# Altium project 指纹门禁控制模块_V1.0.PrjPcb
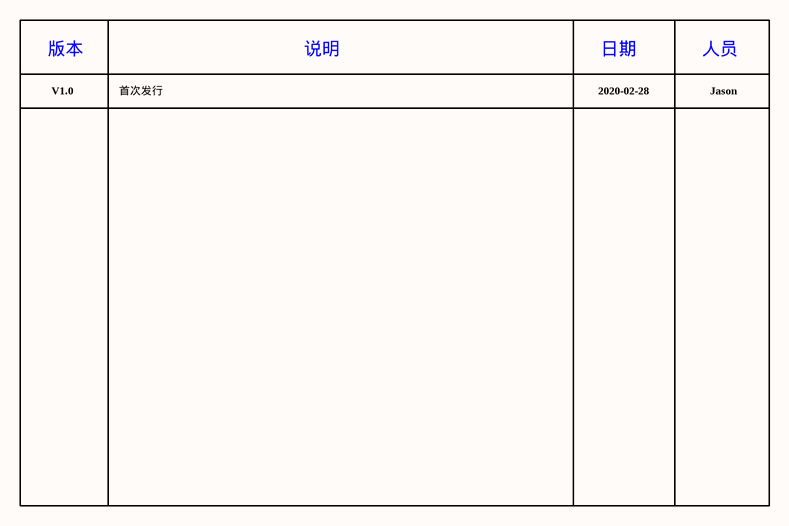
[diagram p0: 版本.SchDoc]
2 sheets, 45 parts. Net scope: global (net labels, ports and power ports of the same name join across sheets).
Board file: 指纹门禁控制模块_V1.0.PcbDoc
Sheets:
  版本.SchDoc
  指纹门禁控制模块_V1.0.SchDoc

## Sheet 版本.SchDoc
size A4

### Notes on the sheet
- 版本
- V1.0
- 首次发行
- 说明
- 2020-02-28
- 日期
- 人员
- Jason

## Sheet 指纹门禁控制模块_V1.0.SchDoc
size A3
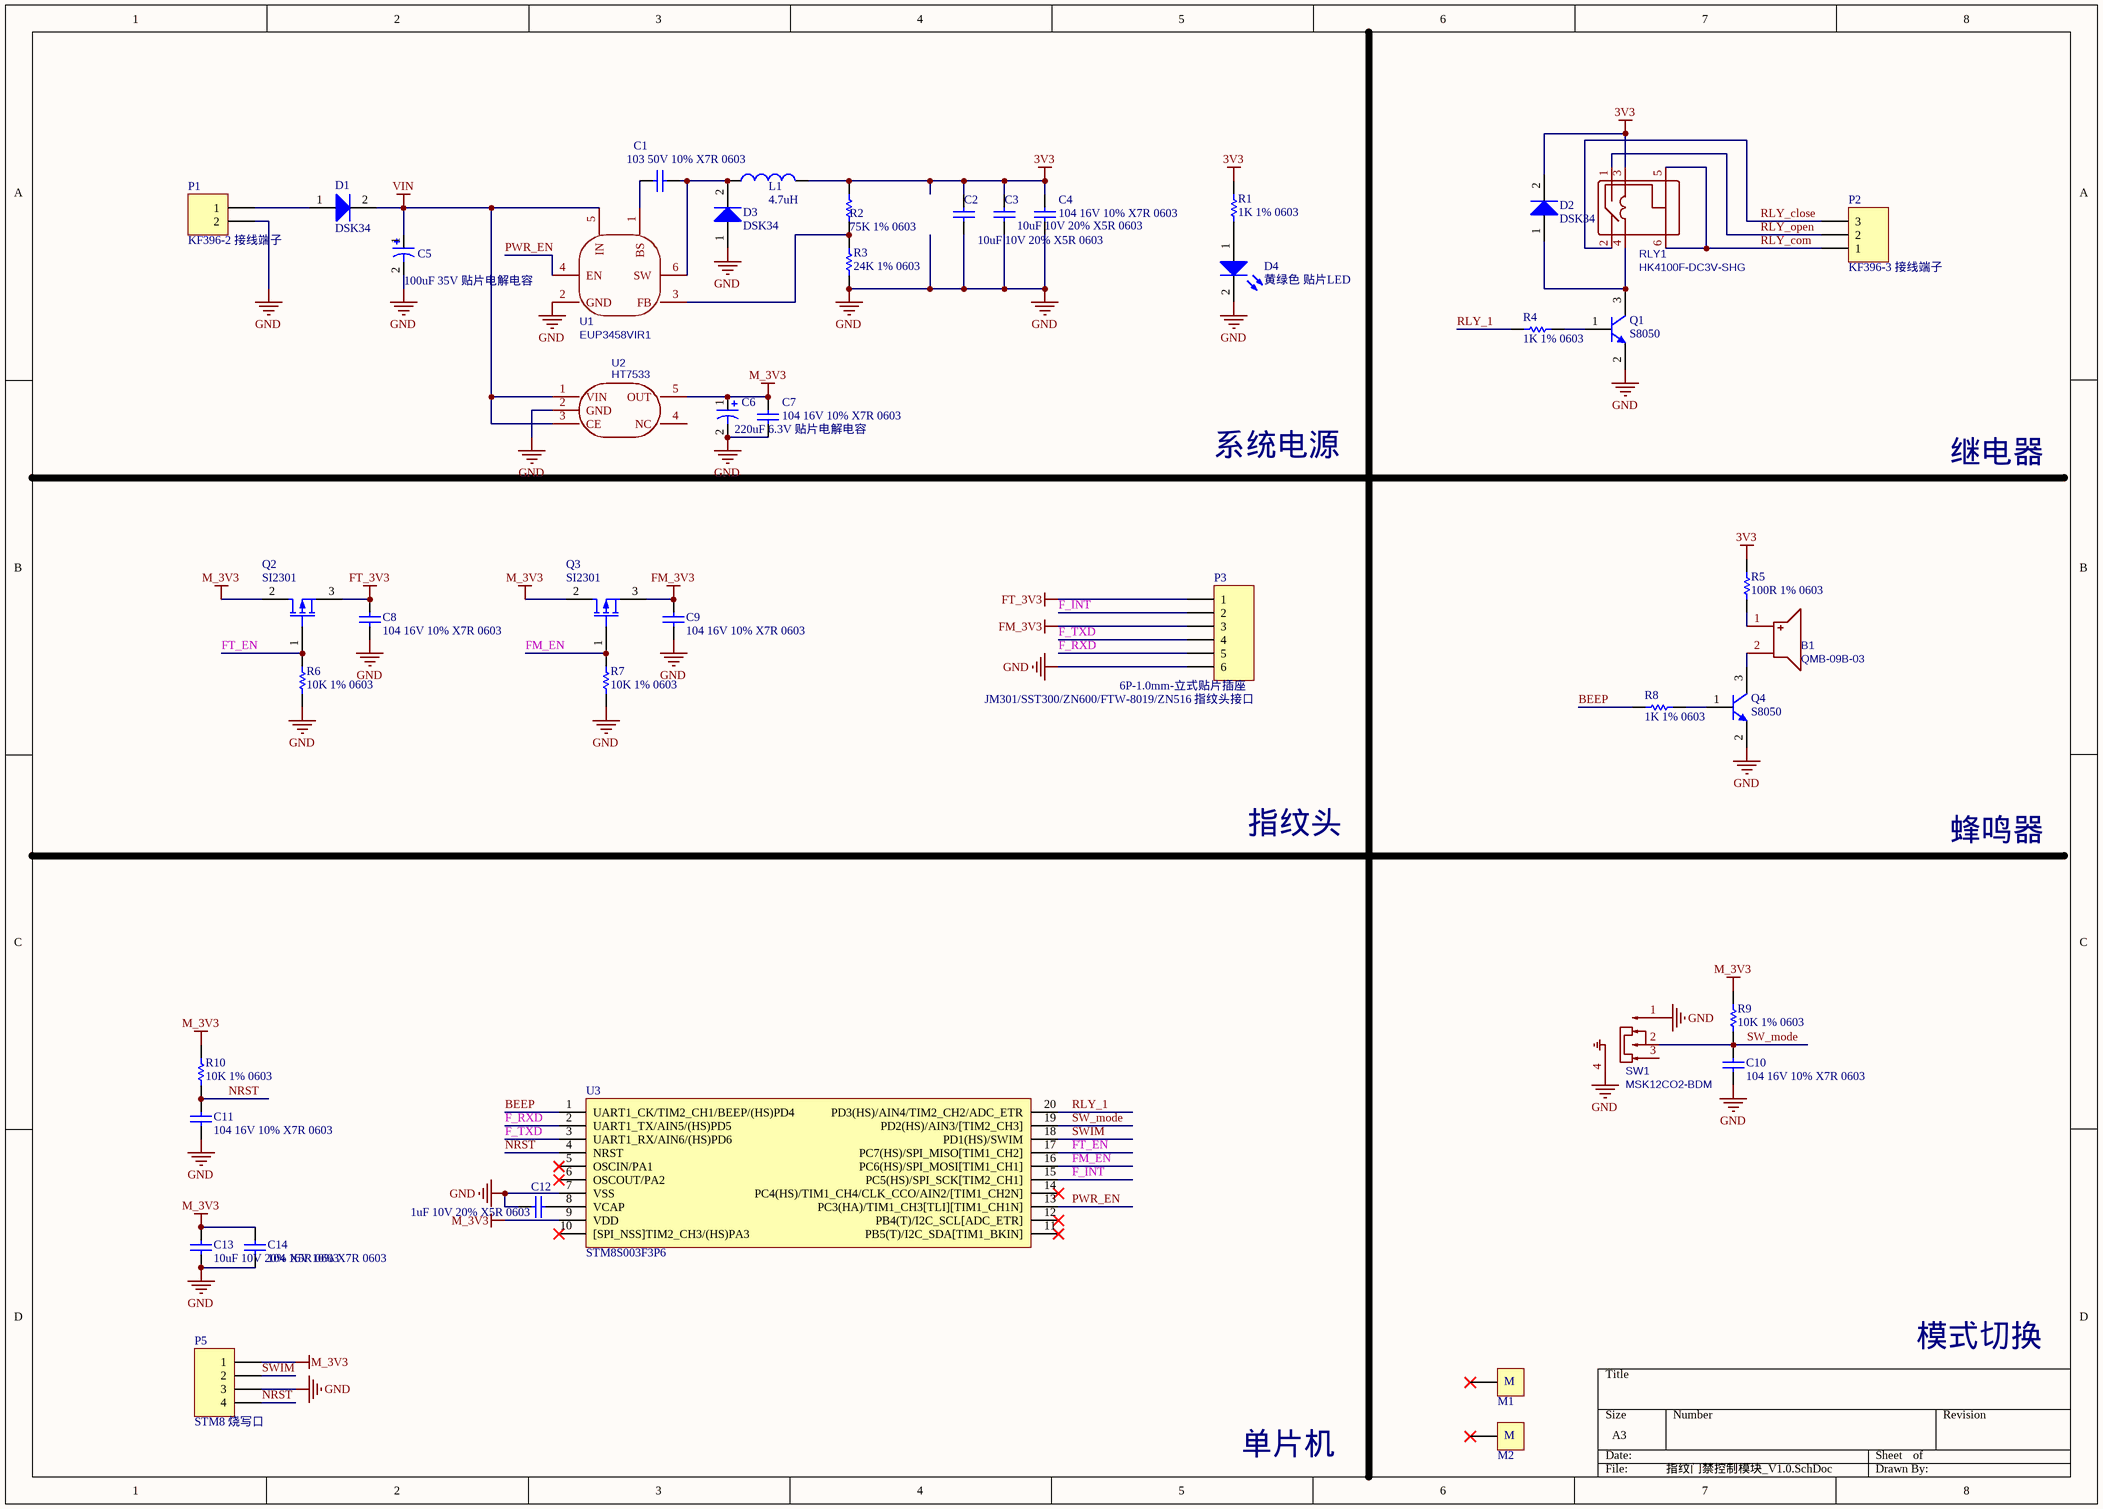
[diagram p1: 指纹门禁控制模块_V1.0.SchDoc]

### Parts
B1  QMB-09B-03  [BUZZER-9MM]
C1  103 50V 10% X7R 0603  [C0603]
C2  10uF 10V 20% X5R 0603  [C0603]
C3  10uF 10V 20% X5R 0603  [C0603]
C4  104 16V 10% X7R 0603  [C0603]
C5  100uF 35V 贴片电解电容  [CAP-D6.3XH7.7]
C6  220uF 6.3V 贴片电解电容  [CAP-D6.3XH7.7]
C7  104 16V 10% X7R 0603  [C0603]
C8  104 16V 10% X7R 0603  [C0603]
C9  104 16V 10% X7R 0603  [C0603]
C10  104 16V 10% X7R 0603  [C0603]
C11  104 16V 10% X7R 0603  [C0603]
C12  1uF 10V 20% X5R 0603  [C0603]
C13  10uF 10V 20% X5R 0603  [C0603]
C14  104 16V 10% X7R 0603  [C0603]
D1  DSK34  [SOD-123]
D2  DSK34  [SOD-123]
D3  DSK34  [SOD-123]
D4  黄绿色 贴片LED  [LED-0603]
L1  4.7uH  [L-SMD-4.5X4.0]
M1  MARK  [MARK]  (value not drawn)
M2  MARK  [MARK]  (value not drawn)
P1  KF396-2 接线端子  [KF396-2]
P2  KF396-3 接线端子  [KF396-3]
P3  6P-1.0mm-立式贴片插座  [SH 1.0_LS_6P]
P5  STM8 烧写口  [HDR1X4]
Q1  S8050  [SOT-23]
Q2  SI2301  [SOT-23]
Q3  SI2301  [SOT-23]
Q4  S8050  [SOT-23]
R1  1K 1% 0603  [R0603]
R2  75K 1% 0603  [R0603]
R3  24K 1% 0603  [R0603]
R4  1K 1% 0603  [R0603]
R5  100R 1% 0603  [R0603]
R6  10K 1% 0603  [R0603]
R7  10K 1% 0603  [R0603]
R8  1K 1% 0603  [R0603]
R9  10K 1% 0603  [R0603]
R10  10K 1% 0603  [R0603]
RLY1  HK4100F-DC3V-SHG  [RELAY-TH_HK4100F-XXX-XXXX]
SW1  MSK12CO2-BDM  [SW-SMD_MSK12CO2-BDM]
U1  EUP3458VIR1  [SOT-23-6]
U2  HT7533  [SOT-23-5]
U3  STM8S003F3P6  [TSSOP-20]

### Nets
3V3: C2.1 C3.1 C4.1 D2.2(K) L1.2 R1.1 R2.1 R5.1 RLY1.3
FM_3V3: C9.1 P3.3 Q3.3(S)
FT_3V3: C8.1 P3.1 Q2.3(S)
GND: C2.2 C3.2 C4.2 C5.2 C6.2 C7.2 C8.2 C9.2 C10.2 C11.1 C12.1 C13.2 C14.1 D3.1(A) D4.2(K) P1.2 P3.6 P5.3 Q1.2(B) Q4.2(B) R3.2 R6.2 R7.2 SW1.1 SW1.4 U1.2(GND) U2.2(GND) U3.7(VSS)
M_3V3: C6.1 C7.1 C13.1 C14.2 P5.1 Q2.2(G) Q3.2(G) R9.1 R10.1 U2.5(OUT) U3.9(VDD)
VIN: C5.1 D1.2(K) U1.5(IN) U2.1(VIN) U2.3(CE)
BEEP: R8.1 U3.1(UART1_CK/TIM2_CH1/BEEP/(HS)PD4)
F_INT: P3.2 U3.15(PC5(HS)/SPI_SCK[TIM2_CH1])
F_RXD: P3.5 U3.2(UART1_TX/AIN5/(HS)PD5)
F_TXD: P3.4 U3.3(UART1_RX/AIN6/(HS)PD6)
FM_EN: Q3.1(D) R7.1 U3.16(PC6(HS)/SPI_MOSI[TIM1_CH1])
FT_EN: Q2.1(D) R6.1 U3.17(PC7(HS)/SPI_MISO[TIM1_CH2])
NRST: C11.2 P5.4 R10.2 U3.4(NRST)
PWR_EN: U1.4(EN) U3.13(PC3(HA)/TIM1_CH3[TLI][TIM1_CH1N])
RLY_1: R4.1 U3.20(PD3(HS)/AIN4/TIM2_CH2/ADC_ETR)
RLY_close: P2.3 RLY1.2
RLY_com: P2.1 RLY1.5 RLY1.6
RLY_open: P2.2 RLY1.1
SW_mode: C10.1 R9.2 SW1.2 U3.19(PD2(HS)/AIN3/[TIM2_CH3])
SWIM: P5.2 U3.18(PD1(HS)/SWIM)
NetB1_1: B1.1 R5.2
NetB1_2: B1.2 Q4.3(E)
NetC1_1: C1.1 U1.1(BS)
NetC1_2: C1.2 D3.2(K) L1.1 U1.6(SW)
NetC12_2: C12.2 U3.8(VCAP)
NetD1_1: D1.1(A) P1.1
NetD2_1: D2.1(A) Q1.3(E) RLY1.4
NetD4_1: D4.1(A) R1.2
NetQ1_1: Q1.1(C) R4.2
NetQ4_1: Q4.1(C) R8.2
NetR2_2: R2.2 R3.1 U1.3(FB)

Not connected (* = marked no-connect by the designer): M1 1*; M2 1*; SW1 3; U2 4(NC); U3 5(OSCIN/PA1)* 6(OSCOUT/PA2)* 10([SPI_NSS]TIM2_CH3/(HS)PA3)* 11(PB5(T)/I2C_SDA[TIM1_BKIN])* 12(PB4(T)/I2C_SCL[ADC_ETR])* 14(PC4(HS)/TIM1_CH4/CLK_CCO/AIN2/[TIM1_CH2N])*

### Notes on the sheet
- 系统电源
- 继电器
- 指纹头
- 蜂鸣器
- 模式切换
- 单片机

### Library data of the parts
B1 = QMB-09B-03: BOM_Manufacturer: HNDZ; Contributor: LCSC; BOM_Paste Type: expand; BOM_Assembly Type: manualWeld
C1-C4 C7-C14 = CapN: CAP; 制造商: SAMSUNG
C5 C6 = CapH: 100uF,35V,插件电解电容; Designer: Anson Chen
D1-D3 = 1N4007
D4 = LED
L1 = InductorDM: MSCD43-4R7MT; Code_IEC: 1005; Value: 10mH
P1 = Header 2: Header, 2-Pin
P2 = Header 3: Header, 3-Pin
P3 = Header 6: Header, 6-Pin
P5 = Header 4: Header, 4-Pin
Q1 Q4 = NPN: NPN晶体管
Q2 Q3 = MOSFET-P
R1-R10 = Res1: Resistor
RLY1 = HK4100F-DC3V-SHG: BOM_Manufacturer: Ningbo Keke New Era Appliance; Contributor: LCSC; BOM_Paste Type: expand; BOM_Assembly Type: manualWeld
SW1 = MSK12CO2-BDM: BOM_Manufacturer: SHOU HAN; Contributor: LCSC
U1 = EUP3458VIR1: BOM_Manufacturer: EUTECH; BOM_Paste Type: recommend; BOM_Assembly Type: smtWeld
U2 = HT7533_C105222: BOM_Manufacturer: HOLTEK; BOM_Manufacturer Part: HT7533-7; Contributor: 立创EDA官方封装库; BOM_Paste Type: expand; BOM_Assembly Type: smtWeld
U3 = STM8S003F3P6: STM8S003F3P6,意法8位单片机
